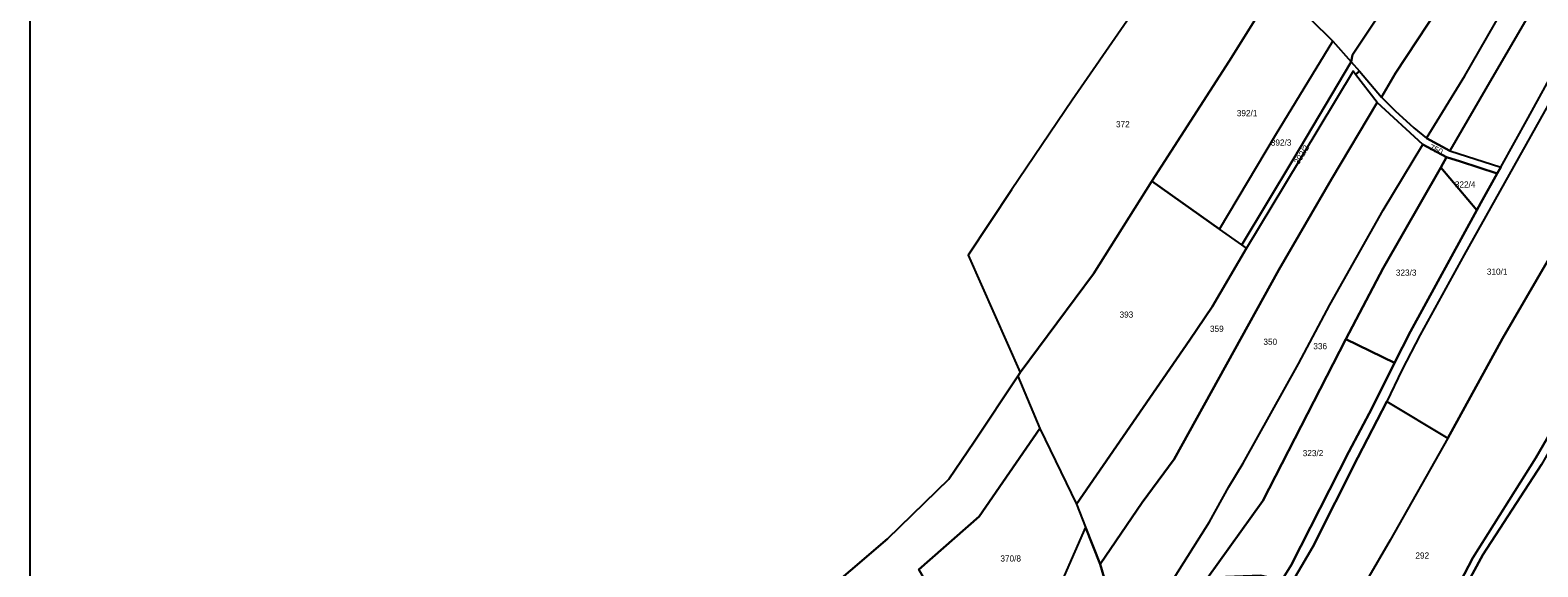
# Model space of a CAD drawing. Extents: x -629983 to -626385, y -1072828 to -1067897.
# Drawn here: x -629983 to -629248, y -1071596 to -1071334 of the extents above; entities that cross this region are included whole.
import ezdxf

# ---------------------------------------------------------------- set-up
doc = ezdxf.new("R2010")
doc.units = 0
for name, color, linetype in [('Default', 7, 'Continuous'), ('Parcela nároku', 7, 'Continuous'), ('Parcelní číslo', 7, 'Continuous'), ('Plocha PÚ', 7, 'Continuous'), ('Převzatý obvod_Ostrov', 7, 'Continuous')]:
    doc.layers.add(name, color=color, linetype=linetype)

msp = doc.modelspace()

# ---------------------------------------------------------------- linework, layer by layer
at = {"layer": 'Default'}
msp.add_lwpolyline([(-629982.64, -1067896.74), (-626385.01, -1067896.74), (-626385.01, -1072827.89), (-629982.64, -1072827.89)], close=True, dxfattribs=at)
at = {"layer": 'Parcela nároku'}
for points in [[(-629294.85, -1071219.25), (-629303.85, -1071238.44), (-629324.52, -1071275.85), (-629358.36, -1071328.63), (-629347.5, -1071339.42), (-629338.48, -1071349.57), (-629337.96, -1071346.05), (-629294.79, -1071281.13), (-629285.17, -1071264.79), (-629267.15, -1071230.1), (-629275.62, -1071225.43), (-629262.93, -1071193.94), (-629238.65, -1071130.37), (-629229.69, -1071103.25), (-629220.42, -1071074.94), (-629206.16, -1071038.51), (-629177.01, -1070970.08), (-629170.42, -1070956.77), (-629190.93, -1070945.74), (-629208.26, -1070986.56), (-629239.55, -1071066.87), (-629258.21, -1071116.1), (-629286.97, -1071186.58), (-629300.05, -1071217.22)], [(-629254.03, -1071330.35), (-629272.83, -1071362.67), (-629290.35, -1071392.92), (-629265.58, -1071400.87), (-629252.25, -1071376.87), (-629224.56, -1071326.33), (-629205.05, -1071279.48), (-629196.24, -1071250.14), (-629213.99, -1071243.83), (-629228.28, -1071278.52), (-629242.88, -1071309.5)], [(-629398.21, -1071292.1), (-629413.19, -1071279.59), (-629414.35, -1071281), (-629447.85, -1071329.61), (-629474.53, -1071368.28), (-629504.23, -1071411.99), (-629525.25, -1071443.82), (-629499.86, -1071501.13), (-629464.21, -1071453.03), (-629435.8, -1071407.84), (-629398.07, -1071349.14), (-629374.96, -1071312.14), (-629387.27, -1071301.19), (-629389.8, -1071298.94)], [(-629374.96, -1071312.14), (-629398.07, -1071349.14), (-629435.8, -1071407.84), (-629402.75, -1071431.14), (-629375.5, -1071385.29), (-629347.5, -1071339.42), (-629358.36, -1071328.63)], [(-629347.5, -1071339.42), (-629338.48, -1071349.57), (-629366.79, -1071397.18), (-629391.89, -1071438.8), (-629402.75, -1071431.14), (-629375.5, -1071385.29)], [(-629370.98, -1071409.77), (-629389.57, -1071440.44), (-629406.27, -1071469.08), (-629417.2, -1071485.19), (-629472.53, -1071565.41), (-629468.08, -1071576.62), (-629460.9, -1071594.7), (-629440.37, -1071564.64), (-629424.88, -1071543.39), (-629373.79, -1071451.1), (-629348.13, -1071406.77), (-629325.79, -1071369.4), (-629336.43, -1071355.62), (-629337.52, -1071354.03)], [(-629338.48, -1071349.57), (-629334.53, -1071354.01), (-629336.43, -1071355.62), (-629337.52, -1071354.03), (-629370.98, -1071409.77), (-629389.57, -1071440.44), (-629391.89, -1071438.8), (-629366.79, -1071397.18)], [(-629290.35, -1071392.92), (-629265.58, -1071400.87), (-629267.42, -1071404.02), (-629285.18, -1071398.12), (-629292.03, -1071396), (-629303.59, -1071389.86), (-629325.79, -1071369.4), (-629336.43, -1071355.62), (-629334.53, -1071354.01), (-629323.75, -1071366.72), (-629317.04, -1071373.47), (-629307.95, -1071381.69), (-629301.82, -1071386.8)], [(-629303.59, -1071389.86), (-629325.79, -1071369.4), (-629348.13, -1071406.77), (-629373.79, -1071451.1), (-629424.88, -1071543.39), (-629440.37, -1071564.64), (-629460.9, -1071594.7), (-629455.6, -1071613.05), (-629447.36, -1071630.2), (-629425.9, -1071603.17), (-629407.61, -1071574.07), (-629398.2, -1071557.05), (-629391.13, -1071545.35), (-629364.25, -1071497), (-629348.88, -1071468.11), (-629322.91, -1071421.93)], [(-629238.91, -1071364.12), (-629246.31, -1071377.46), (-629283.41, -1071443.8), (-629304.96, -1071482.85), (-629313.84, -1071500.04), (-629321.18, -1071515.38), (-629291.47, -1071533.21), (-629264.76, -1071484.55), (-629242.77, -1071446.89), (-629240.38, -1071442.31), (-629207.88, -1071379.91)], [(-629364.25, -1071497), (-629348.88, -1071468.11), (-629322.91, -1071421.93), (-629303.59, -1071389.86), (-629292.03, -1071396), (-629294.77, -1071401.03), (-629322.9, -1071450.3), (-629341.13, -1071484.81), (-629381.58, -1071563.86), (-629408.46, -1071601.17), (-629437.21, -1071639.74), (-629440.19, -1071637.17), (-629447.36, -1071630.2), (-629425.9, -1071603.17), (-629407.61, -1071574.07), (-629398.2, -1071557.05), (-629391.13, -1071545.35)], [(-629285.18, -1071398.12), (-629267.42, -1071404.02), (-629275.3, -1071418.39), (-629277.31, -1071421.87), (-629294.77, -1071401.03), (-629292.03, -1071396)], [(-629341.13, -1071484.81), (-629322.9, -1071450.3), (-629294.77, -1071401.03), (-629277.31, -1071421.87), (-629309.54, -1071481.18), (-629317.33, -1071496.4)], [(-629464.21, -1071453.03), (-629499.86, -1071501.13), (-629501.06, -1071502.9), (-629490.31, -1071528.54), (-629472.53, -1071565.41), (-629417.2, -1071485.19), (-629406.27, -1071469.08), (-629389.57, -1071440.44), (-629391.89, -1071438.8), (-629402.75, -1071431.14), (-629435.8, -1071407.84)], [(-629319.59, -1071583.07), (-629354.09, -1071642.54), (-629358.82, -1071661.92), (-629374.53, -1071683.67), (-629382.5, -1071696.51), (-629352.76, -1071715.65), (-629332.67, -1071684.25), (-629303.81, -1071637.74), (-629295.61, -1071623.18), (-629279.18, -1071591.6), (-629248.48, -1071542.87), (-629235.4, -1071520.09), (-629215.67, -1071483.78), (-629229.28, -1071465.6), (-629242.77, -1071446.89), (-629264.76, -1071484.55), (-629291.47, -1071533.21)], [(-629408.46, -1071601.17), (-629381.58, -1071563.86), (-629341.13, -1071484.81), (-629317.33, -1071496.4), (-629328.34, -1071518.43), (-629339.62, -1071539.85), (-629367.77, -1071595.24), (-629372.32, -1071602.46), (-629382.51, -1071600.23)], [(-629181.93, -1071526.51), (-629213.07, -1071488.18), (-629230.03, -1071518.34), (-629245.72, -1071546.08), (-629274.4, -1071590.15), (-629285.46, -1071610.49), (-629297.99, -1071634.37), (-629324.25, -1071677.09), (-629316.52, -1071720.63), (-629312.72, -1071760.83), (-629294.09, -1071730.4), (-629271.01, -1071689.19), (-629240.34, -1071621.97), (-629196.55, -1071554.87)], [(-629395.57, -1071660.54), (-629385.74, -1071640.97), (-629381.33, -1071627.62), (-629369.96, -1071607.95), (-629357.29, -1071586.31), (-629335.26, -1071542.67), (-629321.18, -1071515.38), (-629291.47, -1071533.21), (-629319.59, -1071583.07), (-629354.09, -1071642.54), (-629358.82, -1071661.92), (-629374.53, -1071683.67), (-629382.5, -1071696.51), (-629392.02, -1071713.23), (-629393.38, -1071723.69), (-629395.42, -1071689.61)], [(-629472.53, -1071565.41), (-629468.08, -1071576.62), (-629483.65, -1071612.31), (-629497.16, -1071626.62), (-629522.05, -1071643.53), (-629549.34, -1071597.4), (-629519.99, -1071571.47), (-629490.31, -1071528.54)], [(-629522.05, -1071643.53), (-629582.14, -1071683.86), (-629609.49, -1071701.62), (-629605.73, -1071714.04), (-629598.98, -1071732.86), (-629539.63, -1071693.13), (-629503.32, -1071662.44), (-629455.6, -1071613.05), (-629460.9, -1071594.7), (-629468.08, -1071576.62), (-629483.65, -1071612.31), (-629497.16, -1071626.62)]]:
    msp.add_lwpolyline(points, close=True, dxfattribs=at)
for points in [[(-629238.65, -1071130.37), (-629262.93, -1071193.94), (-629275.62, -1071225.43), (-629267.15, -1071230.1), (-629285.17, -1071264.79), (-629294.79, -1071281.13), (-629337.96, -1071346.05), (-629338.48, -1071349.57), (-629334.53, -1071354.01), (-629323.75, -1071366.72), (-629316.94, -1071355.08), (-629290.75, -1071315.24), (-629271.98, -1071279.14), (-629259.33, -1071251.95), (-629261.52, -1071250.75), (-629247.58, -1071215.85), (-629216.13, -1071127.98)], [(-629216.13, -1071127.98), (-629247.58, -1071215.85), (-629261.52, -1071250.75), (-629259.33, -1071251.95), (-629271.98, -1071279.14), (-629290.75, -1071315.24), (-629316.94, -1071355.08), (-629323.75, -1071366.72), (-629317.04, -1071373.47), (-629307.95, -1071381.69), (-629301.82, -1071386.8), (-629283.16, -1071356.41), (-629265.14, -1071324.98), (-629253.34, -1071302.99), (-629242.37, -1071278.1)], [(-629242.88, -1071309.5), (-629254.03, -1071330.35), (-629272.83, -1071362.67), (-629290.35, -1071392.92), (-629301.82, -1071386.8), (-629283.16, -1071356.41), (-629265.14, -1071324.98), (-629253.34, -1071302.99), (-629242.37, -1071278.1)], [(-629372.32, -1071602.46), (-629367.77, -1071595.24), (-629339.62, -1071539.85), (-629328.34, -1071518.43), (-629317.33, -1071496.4), (-629309.54, -1071481.18), (-629277.31, -1071421.87), (-629275.3, -1071418.39), (-629267.42, -1071404.02), (-629265.58, -1071400.87), (-629252.25, -1071376.87), (-629224.56, -1071326.33)], [(-629246.31, -1071377.46), (-629283.41, -1071443.8), (-629304.96, -1071482.85), (-629313.84, -1071500.04), (-629321.18, -1071515.38), (-629335.26, -1071542.67), (-629357.29, -1071586.31), (-629369.96, -1071607.95)], [(-629600.74, -1071613.31), (-629564.6, -1071582.35), (-629534.73, -1071553.2), (-629522.37, -1071535.02), (-629501.06, -1071502.9), (-629490.31, -1071528.54), (-629519.99, -1071571.47), (-629549.34, -1071597.4)], [(-629235.4, -1071520.09), (-629248.48, -1071542.87), (-629279.18, -1071591.6), (-629295.61, -1071623.18), (-629303.81, -1071637.74), (-629332.67, -1071684.25), (-629352.76, -1071715.65), (-629350.31, -1071717.22), (-629339.53, -1071701.41), (-629333.41, -1071691.4), (-629327.22, -1071681.73), (-629324.25, -1071677.09), (-629297.99, -1071634.37), (-629285.46, -1071610.49), (-629274.4, -1071590.15), (-629245.72, -1071546.08)]]:
    msp.add_lwpolyline(points, dxfattribs=at)
at = {"layer": 'Plocha PÚ'}
msp.add_lwpolyline([(-629447.85, -1071329.61), (-629474.53, -1071368.28), (-629504.23, -1071411.99), (-629525.25, -1071443.82), (-629499.86, -1071501.13), (-629501.06, -1071502.9), (-629522.37, -1071535.02), (-629534.73, -1071553.2), (-629564.6, -1071582.35), (-629600.74, -1071613.31)], dxfattribs=at)
at = {"layer": 'Převzatý obvod_Ostrov'}
msp.add_lwpolyline([(-629447.85, -1071329.61), (-629474.53, -1071368.28), (-629504.23, -1071411.99), (-629525.25, -1071443.82), (-629499.86, -1071501.13), (-629501.06, -1071502.9), (-629522.37, -1071535.02), (-629534.73, -1071553.2), (-629564.6, -1071582.35), (-629600.74, -1071613.31), (-629611.6, -1071621.75), (-629636.54, -1071638.34), (-629661.58, -1071654.59), (-629669.31, -1071659.36), (-629681.51, -1071666.2), (-629697.6, -1071674.08), (-629715.69, -1071681.07), (-629724.74, -1071684.26), (-629730.67, -1071686.11), (-629736.07, -1071687.36), (-629772.47, -1071696.83), (-629815.31, -1071706.39), (-629865.62, -1071713.17)], dxfattribs=at)

# ---------------------------------------------------------------- texts
at = {"layer": 'Parcelní číslo'}
for s, p in [('392/1', (-629394.29, -1071376.05)), ('372', (-629453.2, -1071381.44)), ('392/3', (-629377.71, -1071390.41)), ('322/4', (-629287.97, -1071410.88)), ('310/1', (-629272.37, -1071453.42)), ('323/3', (-629316.73, -1071453.91)), ('393', (-629451.47, -1071474.39)), ('359', (-629407.38, -1071481.32)), ('350', (-629381.32, -1071487.63)), ('336', (-629356.98, -1071489.8)), ('323/2', (-629362.16, -1071542)), ('292', (-629307.21, -1071592.01)), ('370/8', (-629509.56, -1071593.44))]:
    msp.add_text(s, height=3, dxfattribs=at).set_placement(p)
for s, rotation, p in [('392/2', 58.7403, (-629364.03, -1071399.85)), ('750', 335.22489, (-629300.76, -1071392.28))]:
    msp.add_text(s, height=3, rotation=rotation, dxfattribs=at).set_placement(p)

doc.saveas('drawing.dxf')
